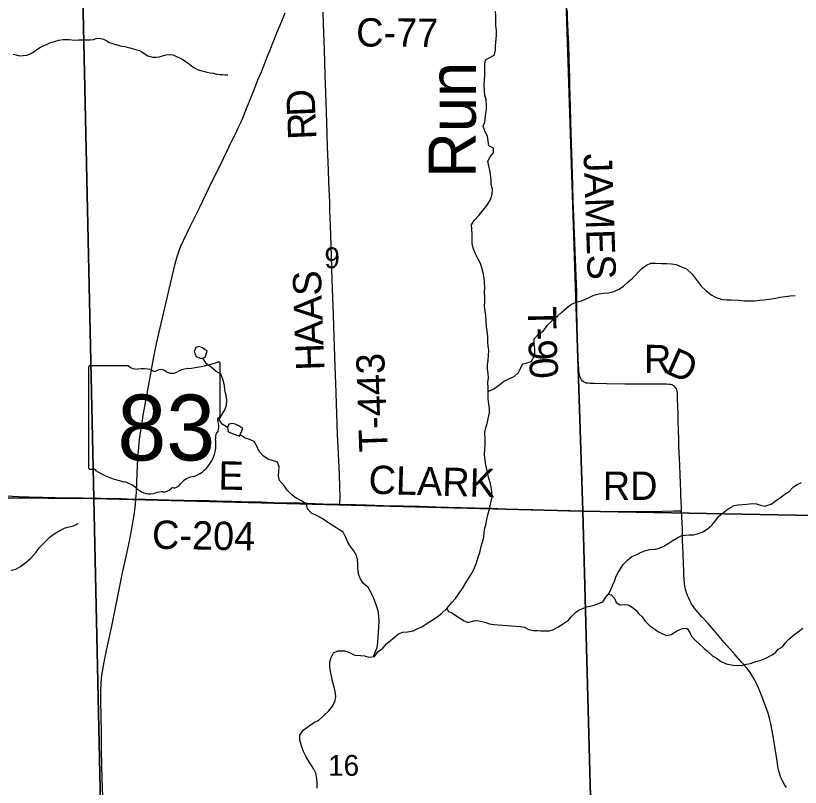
# Model space of a CAD drawing. Extents: x 1985906 to 2360102, y 891258 to 1222054.
# Drawn here: x 2119481 to 2127790, y 979818 to 987986 of the extents above; entities that cross this region are included whole.
import ezdxf

# ---------------------------------------------------------------- set-up
doc = ezdxf.new("R2010")
doc.units = 0
for name, color, linetype in [('GM_X_County_Road', 7, 'Continuous'), ('GM_X_County_Road_Text', 7, 'Continuous'), ('GM_X_Minor_Lake', 7, 'Continuous'), ('GM_X_Minor_River', 7, 'Continuous'), ('GM_X_Minor_River_Text', 7, 'Continuous'), ('GM_X_Section', 7, 'Continuous'), ('GM_X_Section_Text', 7, 'Continuous'), ('GM_X_State_Location', 7, 'Continuous'), ('GM_X_State_Route', 7, 'Continuous'), ('GM_X_State_Shield', 7, 'Continuous'), ('GM_X_Township_Road', 7, 'Continuous'), ('GM_X_Township_Road_Text', 7, 'Continuous')]:
    doc.layers.add(name, color=color, linetype=linetype)

msp = doc.modelspace()

# ---------------------------------------------------------------- linework, layer by layer
at = {"layer": 'GM_X_County_Road'}
for points in [[(2119385.1, 982903.3), (2119510.6, 982897.6), (2119619.8, 982893.2), (2119766.5, 982888.4), (2119897.6, 982884.9), (2120027.4, 982883.6), (2120073.6, 982883.7), (2120186, 982882.2), (2120317.2, 982879.5), (2120382.9, 982877.8), (2120514.3, 982875.2), (2120596.3, 982873.7), (2120662, 982872.1), (2120754.9, 982869.2)], [(2120754.9, 982869.2), (2120787.1, 982868.4), (2120852.8, 982866.9), (2121098.6, 982861.8), (2121426.5, 982855.6), (2121524.9, 982853.6), (2121606.7, 982852.2), (2121770, 982847.8), (2121868.2, 982844.6), (2122081.2, 982838.8), (2122212.1, 982834.4), (2122342.9, 982831.1), (2122490, 982828.2), (2122571.7, 982826), (2122735.5, 982820.5), (2122850.4, 982815.9), (2122914, 982814.1)], [(2122914, 982814.1), (2122997.9, 982811.7), (2123079.8, 982810), (2123194.6, 982807.7), (2123374.8, 982802.7), (2123588, 982796.6), (2123751.9, 982792.4), (2123850.2, 982789.8), (2123932, 982788), (2124062.5, 982784.9), (2124338.9, 982777.5), (2124436.6, 982774.4), (2124518.3, 982771.3), (2124655.5, 982766.9), (2124789.9, 982762.8), (2124960.9, 982757.1), (2125141.2, 982751.3), (2125239.4, 982748.8), (2125337.3, 982746.3), (2125548.7, 982741.5), (2125679.1, 982738.8), (2125793.5, 982736.7), (2125875.4, 982736.3), (2125941, 982736.2), (2126006.5, 982736.2), (2126170.3, 982737), (2126249.5, 982739), (2126329.7, 982740.6), (2126448.5, 982744.1), (2126504.6, 982744.4), (2126532.4, 982744.4)], [(2127642.2, 979816.2), (2127626.4, 979839.9), (2127604.4, 979878.6), (2127585, 979922.6), (2127568.3, 979968.3), (2127562.2, 979989.4), (2127557.8, 980007.9), (2127552.5, 980034.3), (2127546.4, 980073.8), (2127533.2, 980161.8), (2127501.6, 980358.8), (2127489.3, 980435.3), (2127477.9, 980495.1), (2127464.7, 980551.4), (2127446.8, 980612.4), (2127419.1, 980689.4), (2127371.3, 980811.6), (2127333, 980902), (2127304.5, 980960.7), (2127288.5, 980989), (2127261.7, 981029.5), (2127215.9, 981088.8), (2127171.1, 981140.7), (2127099, 981219.8), (2126984.7, 981352.5), (2126877.6, 981476.9), (2126813.1, 981551.3), (2126747.1, 981624.2), (2126703.4, 981673.5), (2126669.1, 981715.9), (2126638.3, 981761.6), (2126622.5, 981789.8), (2126607.6, 981820.5), (2126594.4, 981847.8), (2126583.8, 981876.8), (2126575.9, 981901.4), (2126570.6, 981925.2), (2126568, 981948.1), (2126564.5, 981976.2), (2126556.3, 982065.5), (2126554.9, 982119.6), (2126553.1, 982175.8), (2126549.6, 982289.3), (2126543.1, 982435.8), (2126541.9, 982501.4), (2126541, 982550.6), (2126532.4, 982744.4)]]:
    msp.add_lwpolyline(points, dxfattribs=at)
at = {"layer": 'GM_X_Minor_Lake'}
for points in [[(2121507.6, 984434.7), (2121459.5, 984468.6), (2121421.5, 984482.4), (2121387.6, 984472.2), (2121369.8, 984430.1), (2121392, 984378.1), (2121438, 984362.3), (2121466, 984360.4), (2121487.9, 984370.5)], [(2121487.9, 984370.5), (2121507.6, 984434.7)], [(2121885, 983616.9), (2121844.9, 983644.8), (2121806.9, 983662.6), (2121772.9, 983670.5), (2121737, 983662.3), (2121723.2, 983628.2), (2121731.4, 983580.1), (2121851.4, 983534.6)], [(2121851.4, 983534.6), (2121885, 983616.9)]]:
    msp.add_lwpolyline(points, dxfattribs=at)
at = {"layer": 'GM_X_Minor_River'}
for points in [[(2124450.1, 987144.8), (2124444, 987194.9), (2124442, 987255.1), (2124443.9, 987301.3), (2124447.8, 987359.5), (2124449.7, 987427.7), (2124447.6, 987473.8), (2124457.6, 987517.9), (2124501.5, 987544), (2124547.5, 987568), (2124563.4, 987622.1), (2124563.3, 987668.3), (2124567.2, 987736.5), (2124573.2, 987782.6), (2124571.1, 987826.8), (2124567, 987887), (2124566.9, 987983.3), (2124560.8, 988033.5)], [(2119455.1, 987578.3), (2119485.2, 987570.2), (2119523.1, 987562.2), (2119561.1, 987564.1), (2119601.1, 987568), (2119633.1, 987582), (2119675, 987608.1), (2119715, 987636.1), (2119744.9, 987654.1), (2119784.9, 987672.1), (2119810.9, 987682.1), (2119842.8, 987698.1), (2119890.8, 987714), (2119938.8, 987728), (2119984.7, 987734), (2120012.7, 987733.9), (2120044.7, 987731.9), (2120074.7, 987729.8), (2120100.7, 987727.8), (2120150.7, 987729.7), (2120210.7, 987729.6), (2120244.7, 987731.5), (2120270.6, 987731.5), (2120306.6, 987735.4), (2120332.6, 987743.4), (2120368.6, 987749.4), (2120410.6, 987737.3), (2120444.6, 987719.2), (2120472.6, 987703.1), (2120516.6, 987686.9), (2120576.6, 987670.8), (2120602.6, 987662.7), (2120636.6, 987658.7), (2120662.6, 987652.6), (2120702.6, 987642.5), (2120750.6, 987628.4), (2120792.6, 987616.3), (2120818.6, 987602.2), (2120852.7, 987578), (2120880.7, 987561.9), (2120932.7, 987547.8), (2120968.7, 987545.8), (2121002.7, 987549.7), (2121036.6, 987559.7), (2121072.6, 987569.7), (2121104.6, 987573.6), (2121144.6, 987571.5), (2121184.6, 987555.4), (2121228.6, 987533.3), (2121256.6, 987517.2), (2121286.6, 987497.1), (2121316.7, 987474.9), (2121346.7, 987450.8), (2121374.7, 987432.7), (2121414.7, 987412.6), (2121450.7, 987402.5), (2121480.7, 987396.4), (2121508.7, 987388.3), (2121538.7, 987382.3), (2121572.7, 987376.2), (2121610.7, 987368.1), (2121644.7, 987364.1), (2121670.7, 987362), (2121698.7, 987357.9), (2121726.7, 987357.9)], [(2124213.6, 981922.1), (2124257.4, 982000.3), (2124301.3, 982068.4), (2124333.2, 982124.6), (2124361.1, 982192.8), (2124379, 982252.9), (2124395, 982305.1), (2124410.9, 982367.2), (2124422.8, 982415.4), (2124436.7, 982467.5), (2124440.7, 982517.7), (2124450.6, 982561.8), (2124462.5, 982612), (2124468.4, 982658.1), (2124482.4, 982702.2), (2124496.3, 982750.3), (2124506.2, 982800.5), (2124516.2, 982844.6), (2124526.1, 982892.8), (2124524, 982949), (2124516, 982997.1), (2124505.9, 983043.3), (2124489.8, 983087.5), (2124481.8, 983131.6), (2124469.7, 983183.8), (2124459.6, 983232), (2124451.6, 983280.2), (2124445.5, 983342.4), (2124449.4, 983394.5), (2124453.4, 983444.7), (2124453.3, 983494.8), (2124449.2, 983577.1), (2124459.1, 983623.3), (2124475, 983669.4), (2124485, 983717.5), (2124496.9, 983783.7), (2124496.8, 983827.9), (2124490.7, 983874), (2124482.7, 983930.2), (2124482.6, 983980.4), (2124484.5, 984048.6), (2124482.4, 984102.8), (2124486.3, 984148.9), (2124484.3, 984197.1), (2124478.2, 984243.2), (2124478.2, 984289.4), (2124484.1, 984339.6), (2124488, 984387.7), (2124489.9, 984443.9), (2124485.9, 984488), (2124481.8, 984536.2), (2124479.7, 984586.4), (2124473.6, 984650.6), (2124467.6, 984696.7), (2124461.5, 984754.9), (2124459.4, 984813.1), (2124453.4, 984863.3), (2124445.3, 984909.5), (2124449.2, 984955.6), (2124447.2, 985005.8), (2124445.1, 985053.9), (2124449, 985110.1), (2124446.9, 985164.3), (2124440.9, 985208.5), (2124430.8, 985262.7), (2124416.7, 985316.8), (2124402.7, 985361), (2124378.6, 985407.2), (2124350.5, 985463.4), (2124324.5, 985523.7), (2124314.4, 985573.9), (2124314.2, 985674.2), (2124312.2, 985728.4), (2124308.1, 985772.5), (2124336, 985816.6), (2124386, 985870.7), (2124429.9, 985926.8), (2124469.8, 985976.9), (2124509.7, 986035), (2124527.6, 986097.2), (2124531.5, 986153.4), (2124517.4, 986199.6), (2124515.4, 986249.7), (2124507.3, 986305.9), (2124501.2, 986350.1), (2124491.2, 986394.2), (2124479.1, 986446.4), (2124505, 986490.5), (2124539, 986534.6), (2124540.9, 986584.8), (2124492.9, 986608.9), (2124484.8, 986661.1), (2124476.7, 986709.3), (2124452.7, 986755.5), (2124430.6, 986811.7), (2124448.5, 986863.8), (2124456.4, 986928), (2124468.3, 986992.2), (2124468.3, 987038.4), (2124462.2, 987096.6), (2124450.1, 987144.8)], [(2124483.4, 984009.1), (2124550.5, 984038.5), (2124594.4, 984072.5), (2124646.3, 984114.6), (2124704.3, 984142.5), (2124760.2, 984166.5), (2124804.2, 984208.6), (2124826.1, 984252.7), (2124848, 984298.8), (2124894, 984312.8), (2124941.9, 984326.8), (2124965.9, 984370.9), (2124979.8, 984415), (2124979.7, 984461.1), (2124969.7, 984509.3), (2124969.6, 984565.5), (2125017.5, 984615.6), (2125067.5, 984645.6), (2125111.4, 984709.7), (2125167.3, 984765.8), (2125217.2, 984803.9), (2125269.1, 984849.9), (2125317, 984892), (2125361, 984930), (2125414.9, 984952), (2125470.9, 984968), (2125546.8, 985000), (2125604.7, 985028), (2125658.7, 985041.9), (2125704.7, 985047.9), (2125758.7, 985051.8), (2125814.6, 985067.8), (2125870.6, 985091.7), (2125916.5, 985121.8), (2125962.4, 985163.8), (2126012.4, 985207.9), (2126112.2, 985308.1), (2126162.1, 985346.1), (2126206.1, 985366.1), (2126254.1, 985366), (2126318, 985361.9), (2126372, 985361.8), (2126424, 985359.7), (2126474, 985351.6), (2126532, 985327.4), (2126584, 985305.3), (2126644.1, 985249), (2126696.2, 985180.7), (2126738.2, 985124.4), (2126790.3, 985078.2), (2126844.3, 985032), (2126898.4, 985003.8), (2126960.4, 984981.6), (2127012.4, 984977.5), (2127058.3, 984977.4), (2127146.3, 984973.3), (2127192.3, 984969.2), (2127252.3, 984967.1), (2127304.3, 984969), (2127360.2, 984972.9), (2127404.2, 984978.9), (2127464.2, 984986.8), (2127530.2, 984996.7), (2127574.1, 985004.7), (2127632.1, 985012.6), (2127682.1, 985020.6), (2127736.1, 985024.5)], [(2121723.3, 983627.6), (2121666, 983662), (2121635.9, 983712.2), (2121667.8, 983768.3), (2121695.8, 983814.4), (2121711.7, 983862.5), (2121715.6, 983916.7), (2121711.5, 983966.9), (2121697.5, 984027.1), (2121691.4, 984071.2), (2121675.3, 984139.5), (2121653.2, 984189.7), (2121605.2, 984219.9), (2121547.2, 984268.1), (2121501.1, 984302.3), (2121463.8, 984360.5)], [(2123269.2, 981200.5), (2123288.8, 981247.4), (2123308.7, 981299.6), (2123314.7, 981351.7), (2123320.6, 981405.9), (2123324.5, 981460.1), (2123326.4, 981514.2), (2123328.3, 981576.4), (2123326.3, 981634.6), (2123318.2, 981686.8), (2123302.1, 981739), (2123284.1, 981789.2), (2123268, 981833.4), (2123241.9, 981883.6), (2123211.9, 981931.8), (2123161.8, 981978), (2123127.8, 982028.2), (2123111.7, 982076.4), (2123105.6, 982136.6), (2123105.6, 982184.8), (2123099.5, 982228.9), (2123089.5, 982273.1), (2123063.4, 982321.3), (2123025.3, 982367.5), (2122999.3, 982413.7), (2122977.2, 982461.9), (2122947.2, 982518.1), (2122891.1, 982554.3), (2122831.1, 982592.6), (2122775.1, 982626.8), (2122725, 982665), (2122665, 982695.2), (2122615, 982721.3), (2122570.9, 982767.6), (2122558.9, 982813.7), (2122506.8, 982851.9), (2122452.8, 982880.1), (2122404.8, 982914.3), (2122356.7, 982964.6), (2122320.7, 983014.8), (2122274.6, 983065), (2122262.6, 983111.2), (2122266.5, 983165.4), (2122272.4, 983213.5), (2122252.4, 983259.7), (2122198.3, 983277.8), (2122150.3, 983290), (2122100.3, 983326.2), (2122058.3, 983374.4), (2122036.2, 983428.6), (2122008.1, 983478.8), (2121956.1, 983498.9), (2121910.1, 983515.1), (2121858, 983550.6)], [(2124045.9, 981711.7), (2124064, 981677.6), (2124100, 981663.5), (2124140, 981639.3), (2124184, 981609.1), (2124230, 981581), (2124270, 981562.8), (2124306, 981572.8), (2124348, 981584.8), (2124384, 981580.7), (2124450, 981564.6), (2124500, 981550.4), (2124548, 981540.3), (2124586, 981538.2), (2124638, 981536.2), (2124686, 981532.1), (2124735.9, 981526), (2124775.9, 981523.9), (2124821.9, 981519.8), (2124867.9, 981511.7), (2124915.9, 981487.5), (2124965.9, 981477.4), (2125003.9, 981477.4), (2125041.9, 981475.3), (2125083.9, 981473.2), (2125129.9, 981475.2), (2125177.8, 981487.1), (2125221.8, 981513.1), (2125281.7, 981551.2), (2125333.7, 981589.2), (2125371.6, 981631.3), (2125409.5, 981669.3), (2125449.5, 981695.3), (2125485.4, 981711.3), (2125525.4, 981727.3), (2125565.4, 981735.3), (2125605.3, 981747.3), (2125657.3, 981765.2), (2125697.3, 981783.2), (2125731.2, 981831.3), (2125765.1, 981873.4), (2125785, 981919.5), (2125805, 981961.6), (2125822.9, 982001.7), (2125836.8, 982043.8), (2125858.8, 982088), (2125886.7, 982130), (2125914.6, 982178.2), (2125958.6, 982224.2), (2126006.5, 982260.3), (2126058.4, 982282.3), (2126098.4, 982302.3), (2126144.4, 982320.2), (2126194.3, 982334.2), (2126258.3, 982340.1), (2126300.3, 982354.1), (2126344.2, 982372.1), (2126390.2, 982400.1), (2126434.1, 982428.1), (2126494, 982464.1), (2126534, 982482.1), (2126574, 982488.1), (2126614, 982492), (2126658, 982492), (2126701.9, 982499.9), (2126749.9, 982517.9), (2126803.8, 982549.9), (2126851.7, 982594), (2126887.7, 982636.1), (2126923.6, 982686.2), (2126979.5, 982730.2), (2127025.4, 982766.3), (2127087.4, 982802.3), (2127131.4, 982808.2), (2127175.3, 982812.2), (2127221.3, 982814.1), (2127283.3, 982824), (2127325.3, 982819.9), (2127367.3, 982803.8), (2127413.3, 982795.7), (2127487.2, 982817.7), (2127527.2, 982849.7), (2127567.1, 982873.7), (2127627, 982921.8), (2127663, 982943.8), (2127718.9, 982999.9), (2127754.9, 983021.9), (2127800.8, 983045.9)], [(2119434.9, 982116.6), (2119482.9, 982128.5), (2119532.8, 982156.5), (2119590.8, 982202.6), (2119642.7, 982244.7), (2119698.6, 982306.8), (2119734.5, 982356.9), (2119778.4, 982402.9), (2119844.3, 982465), (2119890.2, 982501.1), (2119950.2, 982537.1), (2120004.1, 982563.1), (2120048.1, 982577.1), (2120094, 982587), (2120142, 982609)], [(2122673, 979807.8), (2122673, 979863.9), (2122668.9, 979910.1), (2122658.8, 979966.3), (2122634.8, 980016.5), (2122592.7, 980080.8), (2122552.6, 980147.1), (2122526.5, 980203.3), (2122506.5, 980257.5), (2122490.4, 980317.7), (2122490.3, 980369.9), (2122526.2, 980424), (2122588.1, 980468), (2122644.1, 980508.1), (2122690, 980530.1), (2122739.9, 980576.2), (2122795.8, 980628.2), (2122837.8, 980682.3), (2122865.7, 980736.5), (2122871.6, 980780.6), (2122865.5, 980832.8), (2122853.5, 980876.9), (2122839.4, 980927.1), (2122827.4, 980979.3), (2122813.3, 981043.5), (2122807.2, 981097.7), (2122809.1, 981147.9), (2122823, 981194), (2122845, 981240.1), (2122890.9, 981262.1), (2122964.9, 981264), (2123016.9, 981243.9), (2123070.9, 981217.7), (2123130.9, 981213.6), (2123174.9, 981209.5), (2123220.9, 981197.4), (2123280.9, 981201.3), (2123318.8, 981257.4), (2123368.7, 981289.4), (2123412.6, 981341.5), (2123490.5, 981405.6), (2123534.5, 981443.7), (2123580.4, 981459.6), (2123628.4, 981463.6), (2123688.4, 981473.5), (2123732.3, 981495.5), (2123780.3, 981517.5), (2123836.2, 981551.5), (2123882.2, 981581.5), (2123940.1, 981617.6), (2123996, 981665.6), (2124045.9, 981711.7), (2124099.8, 981773.8), (2124137.7, 981817.9), (2124175.6, 981872), (2124213.6, 981922.1)], [(2125757.7, 981864.2), (2125787.1, 981857.3), (2125827.2, 981813.1), (2125839.2, 981773), (2125881.2, 981748.8), (2125925.2, 981752.8), (2125965.2, 981750.7), (2126009.2, 981726.5), (2126047.3, 981692.3), (2126079.3, 981656.2), (2126115.3, 981622), (2126143.4, 981579.8), (2126191.4, 981531.6), (2126251.5, 981489.4), (2126289.5, 981463.2), (2126329.5, 981441.1), (2126375.5, 981424.9), (2126421.5, 981434.9), (2126459.5, 981458.9), (2126505.4, 981484.9), (2126551.4, 981502.9), (2126591.4, 981500.8), (2126619.4, 981456.6), (2126637.4, 981418.5), (2126677.5, 981374.3), (2126719.5, 981336.1), (2126771.6, 981285.8), (2126807.6, 981257.7), (2126863.7, 981207.4), (2126899.7, 981187.3), (2126945.7, 981155.1), (2127003.7, 981126.9), (2127079.7, 981110.8), (2127119.7, 981106.7), (2127179.7, 981112.6), (2127219.7, 981120.6), (2127261.6, 981130.5), (2127317.6, 981148.5), (2127365.6, 981160.4), (2127417.5, 981180.4), (2127491.4, 981220.4), (2127527.4, 981244.5), (2127555.3, 981280.5), (2127599.3, 981306.5), (2127629.2, 981342.6), (2127667.2, 981384.7), (2127731.1, 981438.8), (2127771, 981468.8), (2127814.9, 981502.8)]]:
    msp.add_lwpolyline(points, dxfattribs=at)
at = {"layer": 'GM_X_Section'}
for points in [[(2120191.2, 988188.5), (2120308.4, 982876.4), (2114959.2, 982915), (2114813.9, 985659.6), (2114821.5, 988281)], [(2120191.2, 988188.5), (2125310.4, 988140.4), (2125486.3, 982742.6), (2120308.4, 982876.4)], [(2125310.4, 988140.4), (2130622.4, 988007.5), (2130739.9, 982641.3), (2125486.3, 982742.6)], [(2120308.4, 982876.4), (2120423.9, 977532.4), (2115159.2, 977489.5), (2115106.7, 980440.7), (2114959.2, 982915)], [(2125486.3, 982742.6), (2125631.9, 977358.7), (2120423.9, 977532.4), (2120308.4, 982876.4)], [(2130739.9, 982641.3), (2130891.5, 977269.5), (2125631.9, 977358.7), (2125486.3, 982742.6)]]:
    msp.add_lwpolyline(points, close=True, dxfattribs=at)
at = {"layer": 'GM_X_State_Route'}
for points in [[(2121867.4, 986861.2), (2121891.8, 986917.2), (2121919.8, 986987.2), (2121996.1, 987177.5), (2122050, 987312.5), (2122082.9, 987390.2), (2122155.7, 987573.5), (2122169, 987607.8), (2122222.9, 987740), (2122248.1, 987805.1), (2122299.2, 987928.9), (2122333.6, 988015.7)], [(2121204.6, 985475.3), (2121212.8, 985500.6), (2121230.3, 985546.3), (2121256.7, 985606.1), (2121328.8, 985753.3), (2121429.8, 985959.6), (2121522.6, 986151.7), (2121681.6, 986475.7), (2121774.3, 986667.8), (2121817.8, 986756), (2121838.6, 986798.3), (2121856.1, 986835.4), (2121867.4, 986861.2)], [(2120402.9, 979716.7), (2120398, 979913.4), (2120393.7, 980044.5), (2120390.9, 980224.8), (2120389.6, 980405.3), (2120386.3, 980553), (2120382, 980749.8), (2120382, 980848.1), (2120384.7, 980913.4), (2120390.8, 980978.5), (2120399.7, 981043.3), (2120413.6, 981123.8), (2120446.7, 981284.2), (2120498.3, 981524.4), (2120533.8, 981701.2), (2120568.1, 981878.2), (2120612, 982086.8), (2120650.5, 982262.9), (2120684.6, 982423.2), (2120706.3, 982535.8), (2120718.1, 982600.4), (2120734, 982697.6), (2120745.5, 982778.9), (2120754.4, 982860.6), (2120754.9, 982869.2), (2120760.1, 982942.6), (2120768.5, 983139.1), (2120776.2, 983302.7), (2120784.5, 983417), (2120792.9, 983498.4), (2120808.9, 983612), (2120834.6, 983773.7), (2120870.6, 983965.2), (2120905.5, 984159), (2120938.3, 984336.4), (2120970.1, 984497.1), (2120994.1, 984609.3), (2121050.3, 984848.8), (2121110.4, 985104.3), (2121170.8, 985359.7), (2121192.7, 985438.5), (2121204.6, 985475.3)]]:
    msp.add_lwpolyline(points, dxfattribs=at)
at = {"layer": 'GM_X_State_Shield'}
for p, q in [((2121645.3, 983751.8), (2121645.3, 984304.6)), ((2120253.1, 984260.2), (2120253.1, 983203.6)), ((2120674.6, 984278.4), (2120266.8, 984278.4)), ((2121645.2, 983752), (2121645.3, 983751.8))]:
    msp.add_line(p, q, dxfattribs=at)
for centre, radius, start, end in [((2121149.4, 985718.9), 1476.4, 275.84447, 288.90645), ((2121629.9, 984306.9), 15.5, 351.86209, 97.738), ((2120269.1, 984262.5), 16.1, 98.1301, 188.1301), ((2120771.6, 984401), 156.4, 231.61951, 271.11188), ((2120823.5, 983685.2), 561.6, 80.48669, 94.98827), ((2120951, 984267.9), 45.1, 219.79206, 297.10237), ((2121017.3, 984145.8), 93.8, 54.46668, 119.14113), ((2121138.4, 984313.3), 112.9, 233.85621, 294.82819), ((2121337.7, 983955.7), 297, 97.34618, 120.76885), ((2121641.7, 983711.3), 24, 107.94398, 210.33697), ((2121628.8, 983749.7), 16.6, 289.60381, 7.73413), ((2121489.1, 983641.4), 144, 340.03296, 23.64957), ((2121700.8, 983520.5), 104.8, 136.8065, 186.92959), ((2121232.1, 983450.2), 369.3, 292.30889, 8.98584), ((2120269.2, 983201.3), 16.3, 171.95839, 258.30661), ((2120271.7, 983309.4), 124.2, 267.33899, 280.60386), ((2120297.1, 983142.6), 44.8, 29.74838, 93.27175), ((2120862.4, 984091.9), 1066.1, 240.41292, 257.1985), ((2120544.5, 982728.9), 333.6, 47.18416, 75.83597), ((2121387.8, 982906.9), 202.2, 94.40312, 142.57675), ((2120905.3, 983137.4), 211.7, 230.70037, 286.29184), ((2121043.1, 983058.2), 112.8, 268.77702, 315.54927), ((2121145.1, 982955.9), 31.8, 65.75173, 132.64842), ((2121131.6, 983101.2), 119.3, 282.87319, 323.27711), ((2121027.6, 982772), 173.9, 85.69512, 111.20995)]:
    msp.add_arc(centre, radius, start, end, dxfattribs=at)
at = {"layer": 'GM_X_Township_Road'}
for points in [[(2126532.4, 982744.4), (2126531.1, 982784.2), (2126528.1, 982840.4), (2126525.8, 982905.4), (2126524, 982953.3), (2126520.6, 983033.5), (2126516.6, 983130.8), (2126512.5, 983228.8), (2126509.6, 983298.6), (2126508, 983357.7), (2126504.8, 983433.1), (2126502.3, 983510.8), (2126499.1, 983588.6), (2126499.1, 983621.8), (2126496.7, 983671.2), (2126495.9, 983772.4), (2126490.4, 983929), (2126489.7, 983975.3), (2126488.2, 983991.5), (2126485.2, 984010.2), (2126480.9, 984025.3), (2126473.9, 984040.7), (2126463.6, 984054), (2126452.6, 984064.7), (2126436.1, 984073.8), (2126419.9, 984080.2), (2126402, 984082.7), (2126371.7, 984084.5), (2126322.7, 984085.1), (2126267.6, 984084.3), (2126222.9, 984084.1), (2126190, 984084.1), (2126124.6, 984084.4), (2126043.3, 984084.6), (2125995.1, 984084.5), (2125930, 984085.8), (2125736.3, 984090.1), (2125610.7, 984090.9), (2125565.4, 984092.6), (2125540.2, 984095), (2125523.2, 984097.4), (2125506.7, 984101.6), (2125493.1, 984108.9), (2125482.4, 984118.3), (2125474.2, 984130.4), (2125466.2, 984144.2), (2125459.5, 984158.8), (2125454.2, 984173.9), (2125450.2, 984189.5), (2125445.6, 984221.6), (2125442.6, 984254.2), (2125440.7, 984288.6), (2125438.4, 984348.4), (2125436.1, 984381.5), (2125435.2, 984397.8), (2125431.8, 984484.6), (2125428.6, 984577.8), (2125427.4, 984657.5), (2125425.2, 984754.3), (2125424.2, 984819.6), (2125423.4, 984884.8), (2125423.1, 984917.6), (2125422.8, 984950.2), (2125422.8, 984966.6), (2125422.7, 984983), (2125422.5, 984999), (2125421.4, 985064), (2125416, 985227.6), (2125413, 985309.1), (2125408.3, 985422.3), (2125407.9, 985438.8), (2125406.6, 985454.6), (2125405.8, 985470.8), (2125400.7, 985601.7), (2125393.7, 985765.4), (2125390.3, 985863.6), (2125386, 986027.7), (2125381.3, 986191.7), (2125370.3, 986536), (2125366.5, 986634.3), (2125360.3, 986863.5), (2125354.3, 987027.8), (2125353.6, 987125), (2125349.6, 987271.9), (2125347.4, 987337.6), (2125345.4, 987419.5), (2125342.1, 987534.1), (2125337.1, 987681.4), (2125332.1, 987812.4), (2125328.5, 987894.3), (2125325.5, 987959.7), (2125322.6, 988041.5)], [(2122914, 982814.1), (2122914.2, 982818.6), (2122917.6, 982885.3), (2122914.8, 982999.2), (2122910.3, 983129.8), (2122895.6, 983423.8), (2122889.5, 983554.7), (2122881.1, 983767.4), (2122873.6, 983996.4), (2122864.6, 984274.7), (2122855.1, 984585.9), (2122846.4, 984815.1), (2122832.8, 985191.7), (2122825.1, 985437.3), (2122817.1, 985665.4), (2122808.8, 985927.4), (2122805.9, 986009.2), (2122798.1, 986221.9), (2122793.7, 986352.9), (2122790.8, 986434.6), (2122783.9, 986598.3), (2122775.3, 986860.4), (2122764.4, 987171.5), (2122758.3, 987351.6), (2122750, 987627.1), (2122739.1, 987891.1), (2122735.5, 988023.5)]]:
    msp.add_lwpolyline(points, dxfattribs=at)

# ---------------------------------------------------------------- texts
at = {"layer": 'GM_X_County_Road_Text'}
for s, rotation, p in [('C-77', 359.65626, (2123085.8, 987659.8)), ('E', 358.87733, (2121625.6, 982970.5)), ('CLARK', 358.38301, (2123214.9, 982926.6)), ('RD', 0.00001, (2125697.7, 982860.6)), ('C-204', 358.91948, (2120922.4, 982344.6))]:
    msp.add_text(s, height=300, rotation=rotation, dxfattribs=at).set_placement(p)
at = {"layer": 'GM_X_Minor_River_Text'}
msp.add_text('Run', height=500.14, rotation=89.9058, dxfattribs=at).set_placement((2124352.8, 986269.1))
at = {"layer": 'GM_X_Section_Text'}
for s, p in [('9', (2122749.7, 985312.5)), ('16', (2122789.3, 979940.1))]:
    msp.add_text(s, height=221, rotation=0.00001, dxfattribs=at).set_placement(p)
at = {"layer": 'GM_X_State_Location'}
for s in ['s', 'r']:
    msp.add_text(s, height=1, dxfattribs=at).set_placement((2120933.5, 983661.6))
msp.add_text('83', height=1, rotation=0.00001, dxfattribs=at).set_placement((2120681.7, 983588.9))
at = {"layer": 'GM_X_State_Shield'}
msp.add_text('83', height=696.1, dxfattribs=at).set_placement((2120557.9, 983278.1))
at = {"layer": 'GM_X_Township_Road_Text'}
for s, rotation, p in [('D', 92.37579, (2122656, 986925.5)), ('R', 92.57687, (2122667.1, 986679.7)), ('JAMES', 271.9312, (2125494.6, 986523)), ('S', 91.70125, (2122721.4, 985025.1)), ('A', 92.09872, (2122731.1, 984761.9)), ('T', 270.99431, (2124904.2, 984906)), ('A', 92.11064, (2122740.8, 984498.1)), ('-', 271.04841, (2124908.1, 984681.3)), ('H', 92.10964, (2122750.6, 984234.2)), ('9', 271.35073, (2124910.4, 984556.4)), ('R', 359.56678, (2126132.7, 984202.6)), ('D', 335.91842, (2126347.3, 984207.6)), ('T-443', 91.96378, (2123419.6, 983371.3)), ('0', 274.13706, (2124915.5, 984355.8))]:
    msp.add_text(s, height=300, rotation=rotation, dxfattribs=at).set_placement(p)

doc.saveas('drawing.dxf')
